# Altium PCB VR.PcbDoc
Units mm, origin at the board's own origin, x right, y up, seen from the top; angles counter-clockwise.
Board outline 21.97 x 16.51 mm, 2 copper layers (Top Layer, Bottom Layer); 10 components, 8 nets, 40 pads, 10 vias.
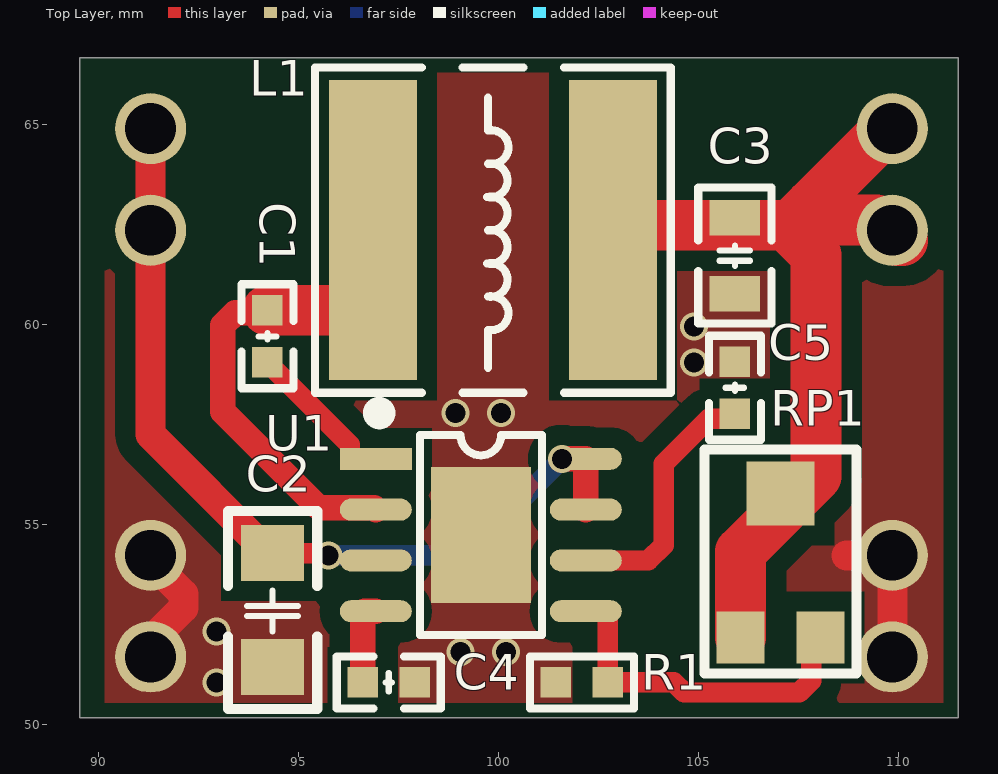
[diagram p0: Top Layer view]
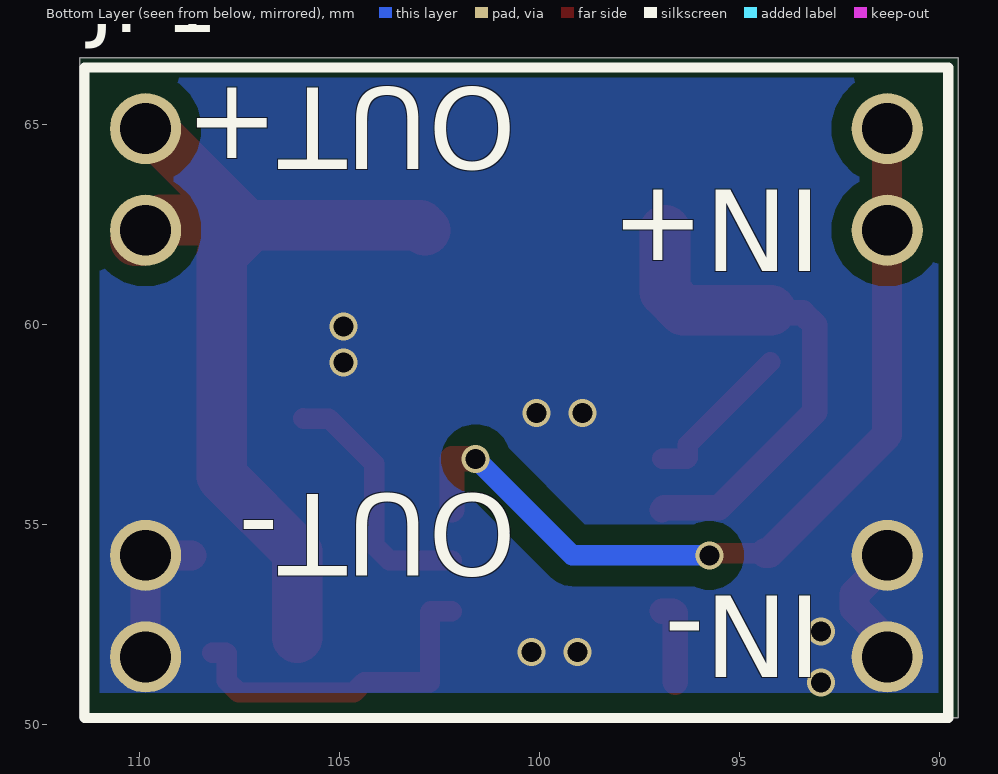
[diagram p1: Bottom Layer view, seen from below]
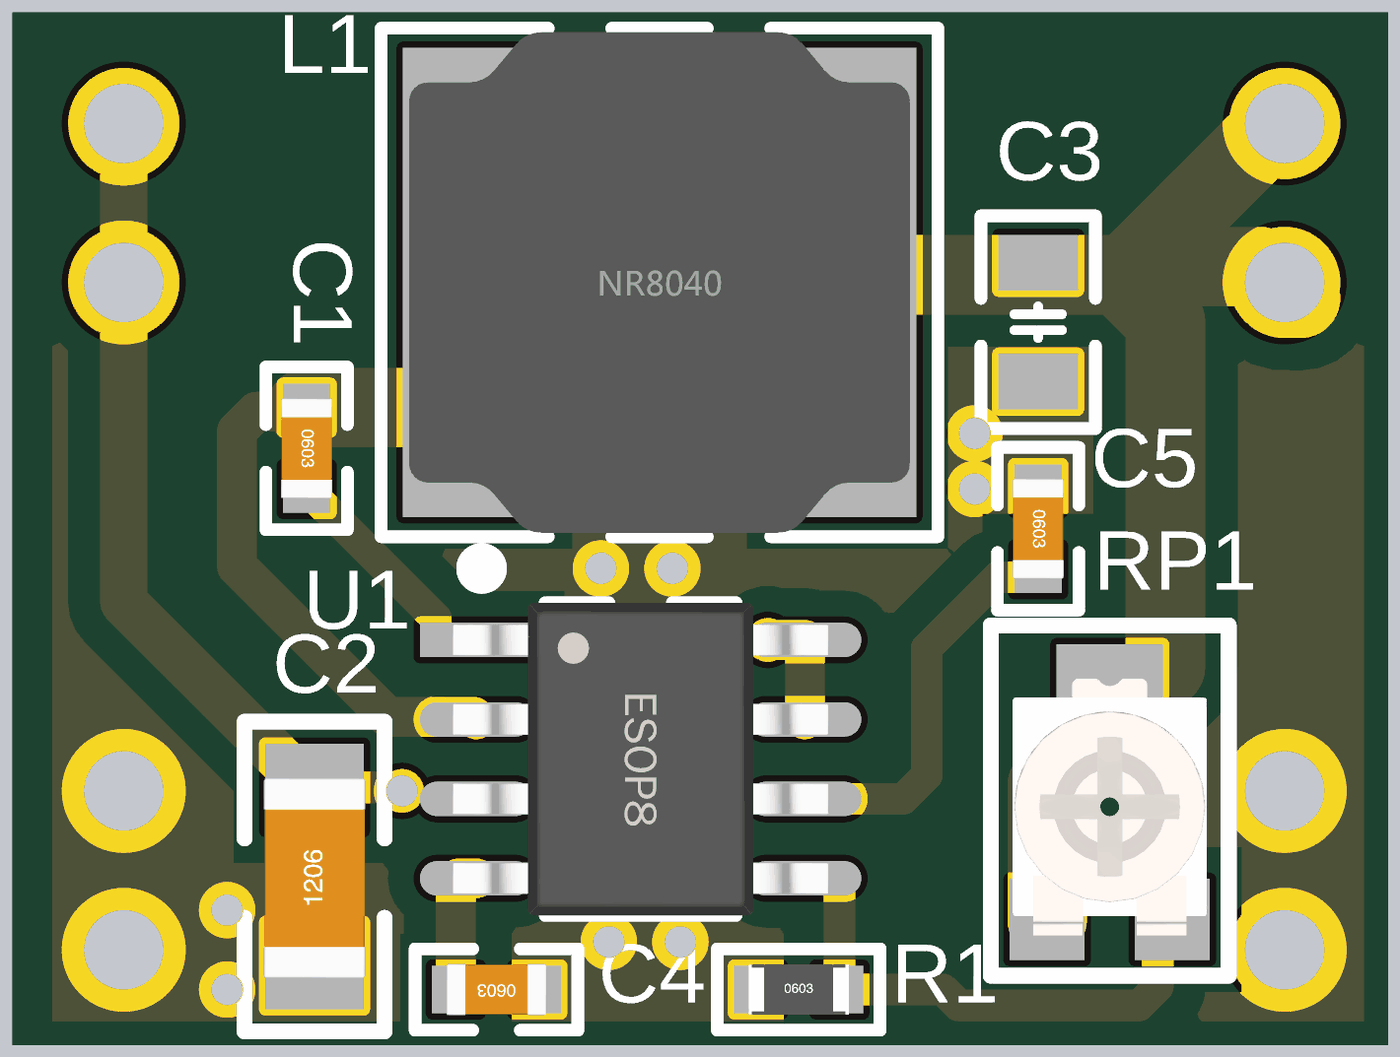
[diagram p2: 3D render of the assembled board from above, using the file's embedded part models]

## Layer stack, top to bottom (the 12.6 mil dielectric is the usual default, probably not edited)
Top Solder: solder mask 0.0102, Solder Resist, Dk 3.5
Top Layer: signal copper 0.0356
Dielectric 1: dielectric 0.32, FR-4, Dk 4.8
Bottom Layer: signal copper 0.0356
Bottom Solder: solder mask 0.0102, Solder Resist, Dk 3.5

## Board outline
89.535,50.165 89.535,66.675 111.506,66.675 111.506,50.165

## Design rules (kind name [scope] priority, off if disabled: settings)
Clearance [All] p1: gap=0.254 ignorepadtopadclearanceinfootprint=FALSE except(0: Arc-Hole Track-Hole SMDPad-Hole THPad-Hole Via-Hole Fill-Hole Poly-Hole Region-Hole Text-Hole; 0.508: Arc-Fill Arc-Poly Arc-Region Track-Fill Track-Poly Track-Region SMDPad-Fill SMDPad-Poly SMDPad-Region THPad-Fill THPad-Poly THPad-Region Via-Fill Via-Poly Via-Region Fill-Fill Fill-Poly Fill-Region Poly-Poly Poly-Region Region-Region)
PolygonConnect [All] p1: connectstyle=Direct reliefconductorwidth=0.254 reliefentries=4 polygonreliefangle="90 Angle" airgapwidth=0.254
RoutingVias [All] p1: holewidth=0.711 width=1.27 viastyle="Through Hole" minholewidth=0.711 minwidth=1.27 maxholewidth=0.711 maxwidth=1.27
SolderMaskExpansion [All] p1: expansion=0.102 istentingtop=FALSE
Width [All] p1: maxlimit=2.54 minlimit=0.254 preferedwidth=0.762 minimp=50.000000 maximp=50.000000 favimp=50.000000
30 further rules are at their usual default settings.

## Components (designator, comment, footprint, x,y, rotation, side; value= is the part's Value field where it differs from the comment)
C1 "104" "C 0603_L" 94.234,59.705 r270 top
C2 "226" "C 1206_L" 94.361,52.835 r90 top
C3 "226" "C 0805_L" 105.918,61.722 r90 top
C4 "104" "C 0603_L" 97.267,51.054 r180 top
C5 "105" "C 0603_L" 105.918,58.42 r270 top
JP1 "Stereye buck module" "Stereye buck module" 100.584,58.293 r0 bottom
L1 "4.7uH" NR8040 99.87,62.357 r0 top
R1 "10K" "R 0603_L" 102.093,51.054 r0 top
RP1 "200K" 3303W 107.061,53.975 r0 top
U1 "SY8204" ESOP8_N 99.568,54.737 r0 top

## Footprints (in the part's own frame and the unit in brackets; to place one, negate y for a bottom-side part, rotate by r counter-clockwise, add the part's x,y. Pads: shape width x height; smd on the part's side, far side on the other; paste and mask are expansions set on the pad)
3303W [mm] "3.5*3.1*1.5mm                          淘宝ID:黄晶宝石"
  rect 1.2x1.3 smd: 1(-1,-1.8) 3(1,-1.8)
  rect 1.7x1.6 smd: 2(0,1.8)
  silkscreen extent -1.9,-2.7 1.9,2.9, body extent -1.55,-2.06 1.55,2.05, height 1.45
"C 0603_L" [mil] "无极性贴片电容                                       淘宝ID:黄晶宝石"
  rect 30x30 smd: 1(-25.59,0) 2(25.59,0)
  silkscreen extent -51,-26 51,26, body extent -31,-16 31,16, height 32
"C 0805_L" [mil] "无极性贴片电容                                        淘宝ID:黄晶宝石"
  rect 35x50 smd: 1(-37.4,0) 2(37.4,0)
  silkscreen extent -67,-36 67,36
"C 1206_L" [mil] "无极性贴片电容"
  rect 55x62 smd: 1(-55.12,0) 2(57.09,0)
  silkscreen extent -96,-44 98,44, body extent -63,-32 63,32, height 48
ESOP8_N [mm] "5*6*1.8mm（长宽高）封装库来自淘宝卖家 ID：黄晶宝石"
  rect 1.8x0.55 smd: 1(-2.625,1.905)
  oval 1.8x0.55 smd: 2(-2.625,0.635) 3(-2.625,-0.635) 4(-2.625,-1.905) 5(2.625,-1.905) 6(2.625,-0.635) 7(2.625,0.635) 8(2.625,1.905)
  rect 2.5x3.4 smd paste-2: 9(0,0)
  rect 0.9x0.7 on Top Paste: 10(-0.625,-1.1) 10(-0.625,0) 10(-0.625,1.1) 11(0.65,-1.1) 11(0.65,0) 11(0.65,1.1)
  silkscreen extent -2.69,-2.5 1.52,3.2, body extent -3,-2.5 3,2.5, height 1.53
NR8040 [mm] "8.0mm*8.0mm*4.0mm(长*宽*高）"
  rect 2.2x7.5 smd: 1(-3,0) 2(3,0)
  silkscreen extent -4.44,-4.06 4.44,4.06, body extent -4,-4 4,4, height 4.1
"R 0603_L" [mil] "1/10W贴片电阻                 淘宝ID:黄晶宝石"
  rect 30x30 smd: 1(-25.59,0) 2(25.59,0)
  silkscreen extent -51,-26 51,26, body extent -31,-16 32,16, height 16
"Stereye buck module" [mil]
  round 70 hole 50: 1(-365,260) 2(-365,160) 3(-365,-160) 4(-365,-260) 5(365,-260) 6(365,-160) 7(365,160) 8(365,260)
  silkscreen extent -425,-320 425,320

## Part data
C1 C2 C3 C4 C5: library part C, "贴片电容"
L1: library part L-NR, "NR磁胶电感"
R1: library part R, "贴片电阻"
RP1: library part RP-SMD, "贴片电位器"
U1: "4.4-30V in, 4A out."

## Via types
v1: diameter 0.7, hole 0.5, Top Layer to Bottom Layer, 10 vias

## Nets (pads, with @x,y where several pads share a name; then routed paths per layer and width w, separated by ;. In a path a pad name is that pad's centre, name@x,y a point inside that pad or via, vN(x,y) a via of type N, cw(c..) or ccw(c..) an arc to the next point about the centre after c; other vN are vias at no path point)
GND: C2.1 C3.1 C4.1 C5.1 JP1.1 JP1.2 JP1.7 JP1.8 R1.1 U1.9 | length 7.1
  Top Layer w0.75: JP1.1@91.313,51.816 91.395,51.734 91.395,52.177 92.133,52.914 92.133,53.258 91.313,54.078 JP1.2@91.313,54.356 ; 108.712,54.229 109.728,54.229 109.855,54.356 JP1.8@109.855,51.816
  other v1: 92.964,51.054 99.06,51.816 100.203,51.816 92.964,52.324 98.933,57.785 100.076,57.785 104.902,59.055 104.902,59.944
NetC1_1: C1.1 L1.1 U1.2 | length 12.6
  Top Layer w0.635: C1.1 94.17,60.292 93.429,60.292 93.12,59.983 93.12,57.82 95.526,55.414 96.9,55.414 U1.2
  Top Layer w1.27: C1.1 96.405,60.355 96.87,60.82 L1.1
NetC1_2: C1.2 U1.1 | length 3.9
  Top Layer w0.508: C1.2 96.297,56.992 96.297,56.663 96.318,56.642 U1.1
NetC4_2: C4.2 U1.4 | length 2.1
  Top Layer w0.635: C4.2 96.617,52.79 96.659,52.832 U1.4
NetC5_2: C5.2 U1.6 | length 6.4
  Top Layer w0.508: U1.6 103.759,54.102 104.14,54.483 104.14,56.515 105.268,57.643 105.903,57.643 C5.2@105.918,57.658
NetR1_2: R1.2 RP1.3 U1.5 | length 8.7
  Top Layer w0.508: U1.5 102.724,52.832 102.743,52.813 R1.2 104.394,51.054 104.648,50.8 107.529,50.8 107.827,51.098 107.827,51.779 107.842,51.794 RP1.3@108.188,51.794
VCC: C2.2 JP1.3 JP1.4 U1.3 U1.7 U1.8 | length 22.2
  Top Layer w0.508: C2.2 v1@95.758,54.285
  Top Layer w0.635: v1(101.6,56.642) U1.8 U1.7
  Top Layer w0.75: JP1.4@91.313,65.024 91.313,62.484 91.313,57.244 94.272,54.285 C2.2
  Bottom Layer w0.508: v1(95.758,54.229) 99.187,54.229 v1(101.6,56.642)
VOUT: C3.2 JP1.5 JP1.6 L1.2 RP1.1 RP1.2 | length 22.1
  Top Layer w1.27: L1.2 102.992,62.479 107.206,62.479 ; RP1.1 106.061,54.317 107.95,56.206 107.95,61.735 107.206,62.479 ; JP1.5@109.855,65.024 107.823,62.992 ; JP1.6@110.109,62.103 109.972,62.103 109.464,62.611 108.204,62.611 107.823,62.992 ; 107.206,62.479 107.31,62.479 107.823,62.992
pads on no net: U1.10 U1.11

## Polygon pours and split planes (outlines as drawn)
GND on Bottom Layer "GND_L02_P001" (solid, remove dead copper, pour order 1): 90.043,66.167 90.043,50.8 110.998,50.8 110.998,66.167
GND on Top Layer "GND_L01_P000" (solid, remove dead copper, pour order 0): 90.17,66.294 90.17,50.546 111.125,50.546 111.125,66.294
